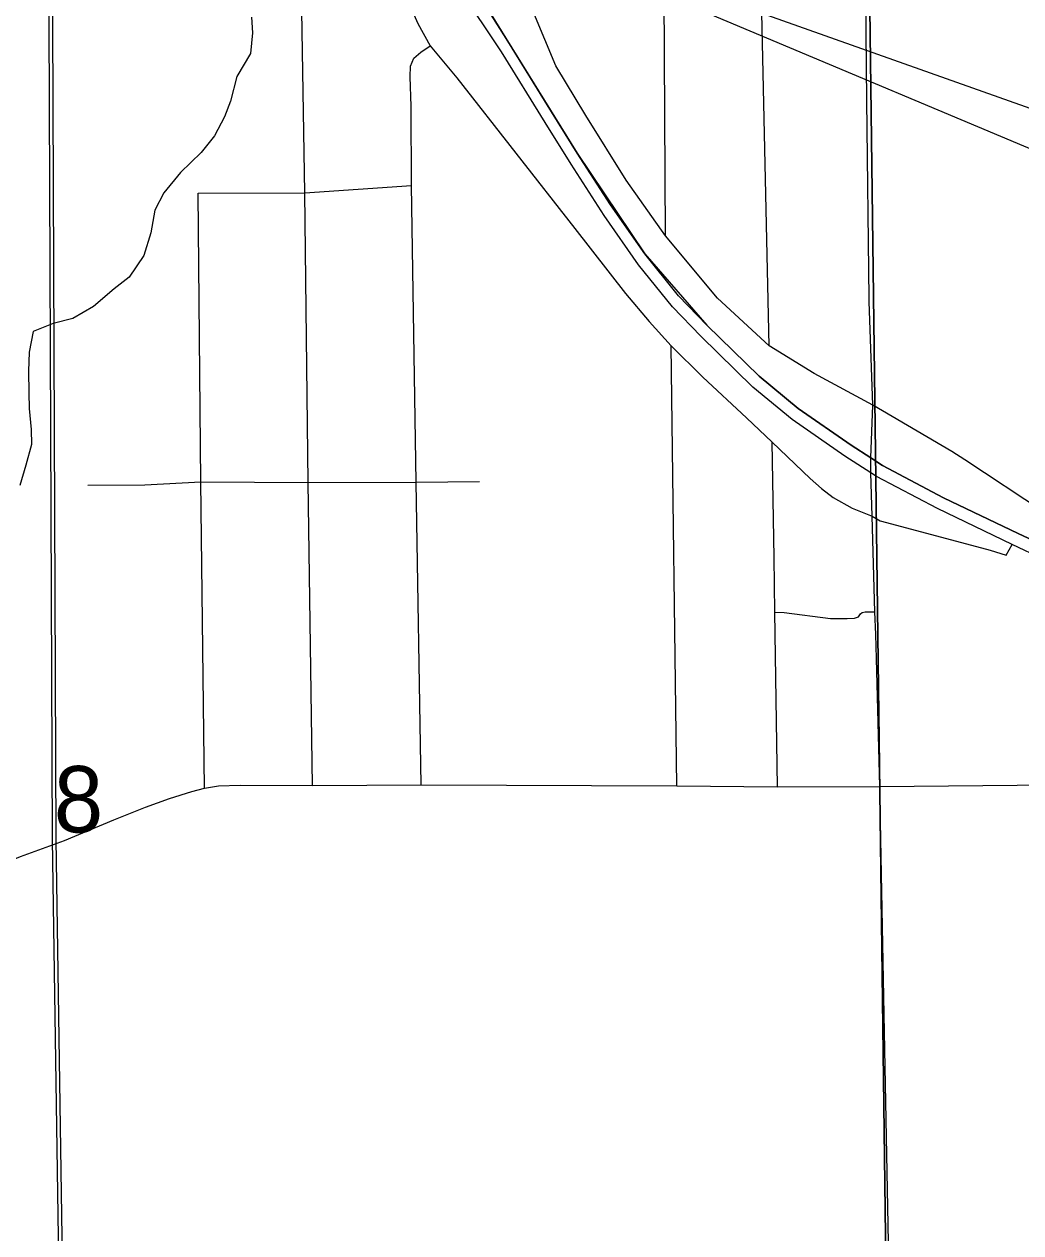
# Model space of a CAD drawing. Extents: x 0 to 40.2, y 0 to 22.
# Drawn here: x 4.597 to 5.226, y 17.901 to 18.665 of the extents above; entities that cross this region are included whole.
import ezdxf

# ---------------------------------------------------------------- set-up
doc = ezdxf.new("R2010")
doc.units = 0
for name, color, linetype in [('GM_X_Adjacent_County_Text', 7, 'Continuous'), ('GM_X_City_Street', 7, 'Continuous'), ('GM_X_Corporation', 7, 'Continuous'), ('GM_X_Major_Lake_Text', 7, 'Continuous'), ('GM_X_Major_River', 7, 'Continuous'), ('GM_X_Major_River_Text', 7, 'Continuous'), ('GM_X_Minor_Lake', 7, 'Continuous'), ('GM_X_Section', 7, 'Continuous'), ('GM_X_Unincorporated', 7, 'Continuous'), ('GM_X_Unincorporated_Location', 7, 'Continuous')]:
    doc.layers.add(name, color=color, linetype=linetype)

msp = doc.modelspace()

# ---------------------------------------------------------------- linework, layer by layer
at = {"layer": 'GM_X_Adjacent_County_Text'}
msp.add_lwpolyline([(4.84272, 18.74972), (4.946, 18.58319), (4.98861, 18.51953), (5.02792, 18.47445), (5.06082, 18.44238), (5.0855, 18.42182), (5.11889, 18.39879), (5.13127, 18.39081), (5.13879, 18.38596), (5.17729, 18.36556), (5.2245, 18.34302), (5.27655, 18.31848), (5.33257, 18.29252), (5.38636, 18.26818), (5.44476, 18.23643), (5.47026, 18.21932), (5.49431, 18.20085)], dxfattribs=at)
at = {"layer": 'GM_X_Corporation'}
for points in [[(5.1306, 18.69122), (6.13405, 18.70621), (6.1533, 17.70056), (5.14342, 17.68519)], [(5.1306, 18.69122), (5.14342, 17.68519), (4.13231, 17.68919), (4.11898, 18.68419)]]:
    msp.add_lwpolyline(points, close=True, dxfattribs=at)
at = {"layer": 'GM_X_Major_Lake_Text'}
for p, q in [((5.12893, 18.6165), (5.12821, 18.6839)), ((5.13028, 18.49134), (5.12893, 18.6165)), ((5.14656, 17.68066), (5.137, 18.18327))]:
    msp.add_line(p, q, dxfattribs=at)
for points in [[(4.83597, 18.68603), (4.84539, 18.66512), (4.8531, 18.65098), (4.87, 18.63072), (4.94441, 18.53557), (4.97643, 18.49457), (4.99139, 18.4769), (5.00532, 18.46157), (5.02526, 18.44175), (5.05292, 18.41591), (5.06903, 18.40062), (5.09296, 18.37775), (5.10021, 18.37138), (5.10761, 18.36578), (5.11951, 18.35899), (5.13219, 18.35388)], [(5.13263, 18.42411), (5.09567, 18.44393), (5.06715, 18.46151), (5.03452, 18.4916), (5.00166, 18.53104), (4.9769, 18.56619), (4.95133, 18.60692), (4.93243, 18.63834), (4.9127, 18.68591)], [(5.13443, 18.2793), (5.13387, 18.29349), (5.13219, 18.35388), (5.13144, 18.3813), (5.13131, 18.38576), (5.13127, 18.39081), (5.13263, 18.42411), (5.1303, 18.48941), (5.13028, 18.49134)], [(5.137, 18.18327), (5.13502, 18.26402), (5.13443, 18.2793)], [(4.65348, 18.16225), (4.65443, 18.16266), (4.67344, 18.17019), (4.68859, 18.1757), (4.70258, 18.18011), (4.71069, 18.18208), (4.71937, 18.18373), (4.73324, 18.18414), (4.77884, 18.18389), (4.84749, 18.18418), (5.00882, 18.18365), (5.07239, 18.18295), (5.137, 18.18327)], [(5.137, 18.18327), (5.33246, 18.18506), (5.34961, 18.18561)], [(4.2452, 18.06942), (4.32552, 18.07145), (4.41046, 18.07409), (4.42659, 18.07516), (4.43976, 18.07722), (4.45244, 18.08051), (4.52166, 18.10956), (4.5945, 18.13892), (4.62221, 18.14903), (4.65348, 18.16225)]]:
    msp.add_lwpolyline(points, dxfattribs=at)
at = {"layer": 'GM_X_Major_River'}
for points in [[(4.62062, 17.42396), (4.6209, 17.73102), (4.61457, 18.14987), (4.61044, 19.18179), (4.60713, 19.57767), (4.60713, 19.63326), (4.61046, 19.67322), (4.61795, 19.71401)], [(4.62295, 17.42396), (4.62323, 17.73104), (4.6169, 18.1499), (4.61277, 19.18181), (4.60946, 19.57768), (4.60946, 19.63316), (4.61277, 19.67292), (4.62022, 19.7135)]]:
    msp.add_lwpolyline(points, dxfattribs=at)
at = {"layer": 'GM_X_Major_River_Text'}
for points in [[(5.19068, 18.38943), (5.18246, 18.39486), (5.13868, 18.42042), (5.13263, 18.42411)], [(5.27655, 18.31848), (5.28155, 18.32844), (5.24095, 18.35619), (5.19068, 18.38943)], [(5.13219, 18.35388), (5.13721, 18.35103), (5.16649, 18.34317), (5.2068, 18.33249), (5.21673, 18.32923), (5.22062, 18.33613)]]:
    msp.add_lwpolyline(points, dxfattribs=at)
at = {"layer": 'GM_X_Minor_Lake'}
msp.add_lwpolyline([(4.74031, 18.66895), (4.74094, 18.65906), (4.73963, 18.64617), (4.7311, 18.63149), (4.7271, 18.61598), (4.72318, 18.60616), (4.71697, 18.5941), (4.70849, 18.58359), (4.69544, 18.57087), (4.68505, 18.55811), (4.67922, 18.54718), (4.67675, 18.53279), (4.67239, 18.51843), (4.66312, 18.50489), (4.65355, 18.49743), (4.64053, 18.48623), (4.62755, 18.47882), (4.61501, 18.47558), (4.60244, 18.47044), (4.6, 18.45757), (4.59946, 18.44543), (4.59965, 18.43176), (4.5999, 18.42188), (4.60123, 18.40858), (4.60148, 18.39908), (4.5979, 18.38622), (4.59394, 18.37337)], dxfattribs=at)
at = {"layer": 'GM_X_Section'}
msp.add_lwpolyline([(9.21768, 17.19882), (9.21806, 16.91071), (4.84272, 18.74972)], close=True, dxfattribs=at)
at = {"layer": 'GM_X_Unincorporated'}
for points in [[(5.31853, 18.28966), (5.22062, 18.33613), (5.1734, 18.35866), (5.13491, 18.37906), (5.13144, 18.3813), (5.11501, 18.39189), (5.08162, 18.41492), (5.05694, 18.43548), (5.02404, 18.46756), (5.00611, 18.48616), (4.98473, 18.51263), (4.96301, 18.54372), (4.94212, 18.57629), (4.92584, 18.60245), (4.8982, 18.64703), (4.87185, 18.6866)], [(5.27655, 18.31848), (5.2245, 18.34302), (5.17729, 18.36556), (5.13879, 18.38596), (5.13127, 18.39081), (5.11889, 18.39879), (5.0855, 18.42182), (5.06082, 18.44238), (5.02792, 18.47445), (5.00999, 18.49306), (4.98861, 18.51953), (4.9669, 18.55062), (4.946, 18.58319), (4.92972, 18.60934), (4.90208, 18.65392), (4.88401, 18.68261)]]:
    msp.add_lwpolyline(points, dxfattribs=at)
at = {"layer": 'GM_X_Unincorporated_Location'}
for p, q in [((5.06715, 18.46151), (5.06239, 18.68369)), ((5.00882, 18.18365), (5.00532, 18.46157))]:
    msp.add_line(p, q, dxfattribs=at)
for points in [[(5.00166, 18.53104), (5.00096, 18.68361), (5.00106, 18.69172), (5.00211, 18.74593), (5.0022, 18.74659), (5.00347, 18.75501), (5.00918, 18.79302), (5.00917, 18.79378), (5.00865, 18.88492), (5.00779, 19.03368)], [(4.77884, 18.18389), (4.7761, 18.37518), (4.77396, 18.55814), (4.77189, 18.68595)], [(4.84749, 18.18418), (4.84436, 18.37547), (4.84124, 18.56273), (4.84111, 18.61286), (4.84058, 18.63138), (4.84074, 18.63817), (4.8428, 18.64306), (4.84729, 18.64701), (4.8531, 18.65098)], [(4.70664, 18.55795), (4.77396, 18.55814), (4.84124, 18.56273)], [(4.71069, 18.18208), (4.70822, 18.37551), (4.70664, 18.55795)], [(5.07239, 18.18295), (5.07084, 18.29332), (5.07041, 18.32792), (5.06903, 18.40062)], [(4.63694, 18.37354), (4.67299, 18.37362), (4.70822, 18.37551), (4.7761, 18.37518), (4.84436, 18.37547), (4.88433, 18.37586)], [(5.07084, 18.29332), (5.07667, 18.29316), (5.10589, 18.28933), (5.1165, 18.28929), (5.12103, 18.28958), (5.12367, 18.29044), (5.12481, 18.29227), (5.12597, 18.29314), (5.12778, 18.29347), (5.13387, 18.29349)]]:
    msp.add_lwpolyline(points, dxfattribs=at)

# ---------------------------------------------------------------- texts
at = {"layer": 'GM_X_City_Street'}
msp.add_text('8', height=0.04186, rotation=0.00001, dxfattribs=at).set_placement((4.61551, 18.15424))

doc.saveas('drawing.dxf')
